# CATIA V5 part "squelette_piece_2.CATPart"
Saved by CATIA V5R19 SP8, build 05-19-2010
Part number: squelette_piece_2
Publications: "Point.8", "Point.7", "Droite.4", "Point.6", "Point.5", "Droite.3", "Point.4", "Point.3", "Droite.2", "Point.2", "Point.1", "Droite.1"
Bounding box of the stored display mesh (mm): x -25 to 50, y 134.7 to 515.7, z -634.7 to -634.7
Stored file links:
  G:\EU_thinkMotion\CFAO_2010\SIL_groupe1\SIL_groupe1\A reprendre\lalpha\lalpha\Alpha.mécanisme\squelette_piece_2.CATPart
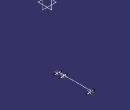
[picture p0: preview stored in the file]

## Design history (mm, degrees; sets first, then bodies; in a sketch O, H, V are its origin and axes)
Set1
  Line1: type PtPt, FirstPoint Point1, SecondPoint Point2, Start 25, End 25
  Point1: stored without definition
  Point2: stored without definition
  Line2: type PtPt, FirstPoint Point3, SecondPoint Point4, Start 25, End 25
  Point3: stored without definition
  Point4: stored without definition
  Line3: type PtPt, FirstPoint Point5, SecondPoint Point6, Start 25, End 25
  Point5: stored without definition
  Point6: stored without definition
  Line4: type PtPt, FirstPoint Point7, SecondPoint Point8
  Point7: stored without definition
  Point8: stored without definition
Body1 (main body)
